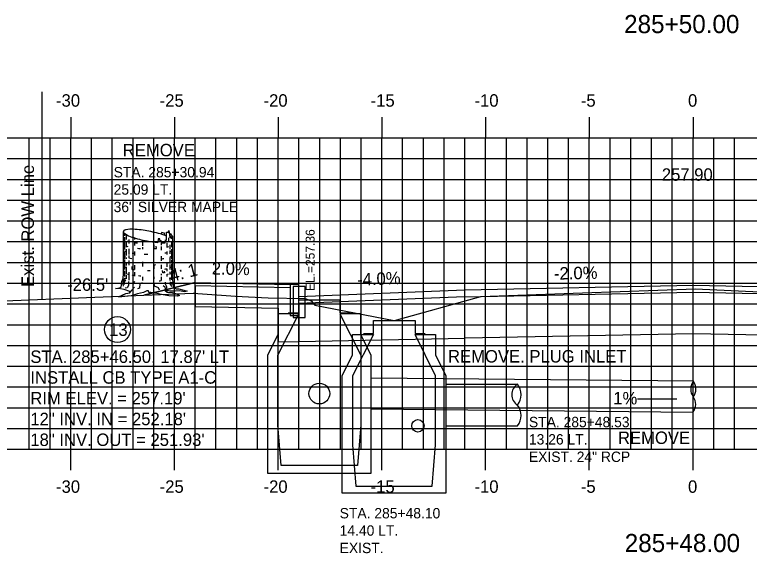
# Model space of a CAD drawing. Extents: x 856680 to 856850, y 366268 to 366378.
# Drawn here: x 856730.41 to 856765.83, y 366297.22 to 366323.17 of the extents above; entities that cross this region are included whole.
import ezdxf

# ---------------------------------------------------------------- set-up
doc = ezdxf.new("R2010")
doc.units = 0
for name, color, linetype in [('ANNOTATION', 7, 'Continuous'), ('D_Curb_Type_1_Lt', 7, 'Continuous'), ('D_Drainage_CB_TypeA1-B1', 7, 'Continuous'), ('D_Drainage_Culvert', 7, 'Continuous'), ('D_Drainage_Text', 7, 'Continuous'), ('D_Roadway_Centerline_Text', 7, 'Continuous'), ('D_Roadway_Edge_Shoulder', 7, 'Continuous'), ('D_Roadway_FinishedGrade', 7, 'Continuous'), ('D_Roadway_Sidewalks_Paved', 7, 'Continuous'), ('D_Roadway_SubGrade', 7, 'Continuous'), ('D_Text_Monospaced', 7, 'Continuous'), ('D_Text_Standard', 7, 'Continuous'), ('E_ROW_Line', 7, 'Continuous'), ('H_V ANNOTATION', 7, 'Continuous'), ('JUNK FILL', 7, 'Continuous'), ('MAJOR', 7, 'Continuous'), ('MINOR', 7, 'Continuous'), ('PDRAIN', 7, 'Continuous'), ('S_Curb_Type_2', 7, 'Continuous'), ('S_Drainage_CB', 7, 'Continuous'), ('S_Drainage_Culvert_Top', 7, 'Continuous'), ('S_Drainage_Invert', 7, 'Continuous'), ('S_Roadway_Centerline', 7, 'Continuous'), ('S_Trees_Decid_Pay', 7, 'Continuous')]:
    doc.layers.add(name, color=color, linetype=linetype)

msp = doc.modelspace()

# ---------------------------------------------------------------- linework, layer by layer
at = {"layer": 'ANNOTATION'}
msp.add_line((856760.442, 366304.662), (856762.341, 366304.662), dxfattribs=at)
at = {"layer": 'D_Curb_Type_1_Lt'}
msp.add_lwpolyline([(856743.7, 366310.179), (856743.7, 366308.679), (856744.116, 366308.679), (856744.116, 366310.179)], close=True, dxfattribs=at)
at = {"layer": 'D_Drainage_CB_TypeA1-B1'}
for p, q in [((856743.099, 366308.761), (856743.099, 366307.744)), ((856743.099, 366306.76), (856744.116, 366308.761)), ((856744.116, 366308.761), (856743.099, 366308.761)), ((856747.102, 366308.761), (856746.085, 366308.761)), ((856746.085, 366308.761), (856747.102, 366306.76)), ((856747.102, 366307.744), (856747.102, 366308.761)), ((856743.099, 366307.744), (856742.607, 366306.76)), ((856747.594, 366306.76), (856747.102, 366307.744)), ((856742.607, 366306.76), (856742.607, 366301.084)), ((856743.099, 366303.414), (856743.099, 366306.76)), ((856747.102, 366306.76), (856747.102, 366303.414)), ((856747.594, 366301.084), (856747.594, 366306.76)), ((856743.263, 366301.445), (856743.099, 366303.414)), ((856747.102, 366303.414), (856746.938, 366301.445)), ((856746.938, 366301.445), (856743.263, 366301.445)), ((856742.607, 366301.084), (856747.594, 366301.084))]:
    msp.add_line(p, q, dxfattribs=at)
msp.add_lwpolyline([(856743.591, 366308.803), (856744.116, 366308.803), (856744.116, 366309.426), (856746.085, 366309.426), (856746.085, 366308.803), (856746.61, 366308.803)], dxfattribs=at)
at = {"layer": 'D_Drainage_Culvert'}
for p, q in [((856763.132, 366305.511), (856747.609, 366305.666)), ((856763.117, 366304.011), (856747.594, 366304.166))]:
    msp.add_line(p, q, dxfattribs=at)
for centre, radius, start, end in [((856763.628, 366305.131), 0.625, 142.5572, 216.297), ((856762.615, 366305.137), 0.638, 323.5548, 35.9163), ((856762.629, 366304.394), 0.617, 321.892, 36.5542)]:
    msp.add_arc(centre, radius, start, end, dxfattribs=at)
at = {"layer": 'D_Drainage_Text'}
msp.add_circle((856735.365, 366307.999), 0.625, dxfattribs=at)
at = {"layer": 'D_Roadway_Edge_Shoulder'}
msp.add_lwpolyline([(856744.116, 366309.596), (856752.116, 366309.916), (856763.116, 366310.136), (856774.116, 366309.916), (856782.117, 366309.596)], dxfattribs=at)
at = {"layer": 'D_Roadway_FinishedGrade'}
msp.add_line((856736.635, 366309.652), (856739.111, 366310.271), dxfattribs=at)
at = {"layer": 'D_Roadway_Sidewalks_Paved'}
msp.add_lwpolyline([(856739.111, 366310.271), (856743.7, 366310.179), (856743.7, 366310.012), (856739.111, 366310.104)], close=True, dxfattribs=at)
at = {"layer": 'D_Roadway_SubGrade'}
msp.add_lwpolyline([(856739.111, 366310.104), (856739.111, 366309.104), (856743.116, 366309.024), (856743.116, 366307.402), (856744.116, 366307.422)], dxfattribs=at)
for points in [[(856752.116, 366307.582), (856752.116, 366309.582), (856763.116, 366309.802), (856774.116, 366309.582), (856774.116, 366307.582), (856763.116, 366307.802)], [(856752.116, 366309.582), (856744.116, 366309.262), (856744.116, 366307.422), (856752.116, 366307.582)]]:
    msp.add_lwpolyline(points, close=True, dxfattribs=at)
at = {"layer": 'E_ROW_Line'}
msp.add_line((856731.739, 366309.453), (856731.739, 366319.453), dxfattribs=at)
at = {"layer": 'JUNK FILL'}
msp.add_lwpolyline([(856739.116, 366309.749), (856739.116, 366310.271), (856739.111, 366310.271), (856736.635, 366309.652), (856739.021, 366309.749)], close=True, dxfattribs=at)
at = {"layer": 'MAJOR'}
for p, q in [((856733.116, 366318.238), (856733.116, 366317.236)), ((856738.116, 366318.238), (856738.116, 366317.236)), ((856743.116, 366318.238), (856743.116, 366317.236)), ((856748.116, 366318.238), (856748.116, 366317.236)), ((856753.116, 366318.238), (856753.116, 366317.236)), ((856758.116, 366318.238), (856758.116, 366317.236)), ((856763.116, 366318.238), (856763.116, 366317.236)), ((856693.116, 366317.236), (856833.116, 366317.236)), ((856693.116, 366317.236), (856833.116, 366317.236)), ((856733.116, 366302.236), (856733.116, 366317.236)), ((856738.116, 366302.236), (856738.116, 366317.236)), ((856743.116, 366302.236), (856743.116, 366317.236)), ((856748.116, 366302.236), (856748.116, 366317.236)), ((856753.116, 366302.236), (856753.116, 366317.236)), ((856758.116, 366302.236), (856758.116, 366317.236)), ((856763.116, 366302.236), (856763.116, 366317.236)), ((856693.116, 366312.236), (856833.116, 366312.236)), ((856693.116, 366307.236), (856833.116, 366307.236)), ((856693.116, 366302.236), (856833.116, 366302.236)), ((856693.116, 366302.236), (856833.116, 366302.236)), ((856733.116, 366301.234), (856733.116, 366302.236)), ((856738.116, 366301.234), (856738.116, 366302.236)), ((856743.116, 366301.234), (856743.116, 366302.236)), ((856748.116, 366301.234), (856748.116, 366302.236)), ((856753.116, 366301.234), (856753.116, 366302.236)), ((856758.116, 366301.234), (856758.116, 366302.236)), ((856763.116, 366301.234), (856763.116, 366302.236))]:
    msp.add_line(p, q, dxfattribs=at)
at = {"layer": 'MINOR'}
for p, q in [((856731.116, 366302.236), (856731.116, 366317.236)), ((856732.116, 366302.236), (856732.116, 366317.236)), ((856734.116, 366302.236), (856734.116, 366317.236)), ((856735.116, 366302.236), (856735.116, 366317.236)), ((856736.116, 366302.236), (856736.116, 366317.236)), ((856737.116, 366302.236), (856737.116, 366317.236)), ((856739.116, 366302.236), (856739.116, 366317.236)), ((856740.116, 366302.236), (856740.116, 366317.236)), ((856741.116, 366302.236), (856741.116, 366317.236)), ((856742.116, 366302.236), (856742.116, 366317.236)), ((856744.116, 366302.236), (856744.116, 366317.236)), ((856745.116, 366302.236), (856745.116, 366317.236)), ((856746.116, 366302.236), (856746.116, 366317.236)), ((856747.116, 366302.236), (856747.116, 366317.236)), ((856749.116, 366302.236), (856749.116, 366317.236)), ((856750.116, 366302.236), (856750.116, 366317.236)), ((856751.116, 366302.236), (856751.116, 366317.236)), ((856752.116, 366302.236), (856752.116, 366317.236)), ((856754.116, 366302.236), (856754.116, 366317.236)), ((856755.116, 366302.236), (856755.116, 366317.236)), ((856756.116, 366302.236), (856756.116, 366317.236)), ((856757.116, 366302.236), (856757.116, 366317.236)), ((856759.116, 366302.236), (856759.116, 366317.236)), ((856760.116, 366302.236), (856760.116, 366317.236)), ((856761.116, 366302.236), (856761.116, 366317.236)), ((856762.116, 366302.236), (856762.116, 366317.236)), ((856764.116, 366302.236), (856764.116, 366317.236)), ((856765.116, 366302.236), (856765.116, 366317.236)), ((856693.116, 366316.236), (856833.116, 366316.236)), ((856693.116, 366315.236), (856833.116, 366315.236)), ((856693.116, 366314.236), (856833.116, 366314.236)), ((856693.116, 366313.236), (856833.116, 366313.236)), ((856693.116, 366311.236), (856833.116, 366311.236)), ((856693.116, 366310.236), (856833.116, 366310.236)), ((856693.116, 366309.236), (856833.116, 366309.236)), ((856693.116, 366308.236), (856833.116, 366308.236)), ((856693.116, 366306.236), (856833.116, 366306.236)), ((856693.116, 366305.236), (856833.116, 366305.236)), ((856693.116, 366304.236), (856833.116, 366304.236)), ((856693.116, 366303.236), (856833.116, 366303.236))]:
    msp.add_line(p, q, dxfattribs=at)
at = {"layer": 'PDRAIN'}
msp.add_circle((856745.1, 366304.916), 0.5, dxfattribs=at)
at = {"layer": 'S_Curb_Type_2'}
msp.add_lwpolyline([(856744.423, 366310.081), (856743.839, 366310.081), (856743.839, 366308.581), (856744.423, 366308.581)], close=True, dxfattribs=at)
at = {"layer": 'S_Drainage_CB'}
for p, q in [((856746.697, 366306.782), (856746.697, 366307.766)), ((856746.697, 366307.766), (856747.714, 366307.766)), ((856747.714, 366307.766), (856746.697, 366305.765)), ((856749.716, 366307.766), (856750.7, 366307.766)), ((856750.7, 366305.765), (856749.716, 366307.766)), ((856750.7, 366307.766), (856750.7, 366306.782)), ((856746.205, 366305.765), (856746.697, 366306.782)), ((856750.7, 366306.782), (856751.192, 366305.765)), ((856746.205, 366300.122), (856746.205, 366305.765)), ((856746.697, 366305.765), (856746.697, 366302.451)), ((856750.7, 366302.451), (856750.7, 366305.765)), ((856751.192, 366305.765), (856751.192, 366300.122)), ((856746.697, 366302.451), (856746.861, 366300.45)), ((856750.536, 366300.45), (856750.7, 366302.451)), ((856746.861, 366300.45), (856750.536, 366300.45)), ((856751.192, 366300.122), (856746.205, 366300.122))]:
    msp.add_line(p, q, dxfattribs=at)
msp.add_lwpolyline([(856747.222, 366307.808), (856747.714, 366307.808), (856747.714, 366308.431), (856749.716, 366308.431), (856749.716, 366307.808), (856750.208, 366307.808)], dxfattribs=at)
at = {"layer": 'S_Drainage_Culvert_Top'}
for p, q in [((856751.192, 366305.363), (856754.658, 366305.363)), ((856751.192, 366303.363), (856754.658, 366303.363))]:
    msp.add_line(p, q, dxfattribs=at)
for centre, radius, start, end in [((856754.955, 366304.863), 0.582, 120.7154, 239.2846), ((856753.991, 366304.863), 0.833, 323.1301, 36.8699), ((856753.991, 366303.863), 0.833, 323.1301, 36.8699)]:
    msp.add_arc(centre, radius, start, end, dxfattribs=at)
at = {"layer": 'S_Drainage_Invert'}
msp.add_circle((856749.853, 366303.363), 0.3, dxfattribs=at)
at = {"layer": 'S_Roadway_Centerline'}
msp.add_lwpolyline([(856729.519, 366309.362), (856739.021, 366309.749), (856741.05, 366309.607), (856742.639, 366309.528), (856744.423, 366309.498), (856744.707, 366309.391), (856744.882, 366309.174), (856748.7, 366308.435), (856748.73, 366308.436), (856752.889, 366309.59), (856757.791, 366309.768), (856763.242, 366309.958), (856768.411, 366309.721)], dxfattribs=at)
at = {"layer": 'S_Trees_Decid_Pay'}
for p, q in [((856735.702, 366312.63), (856735.702, 366312.51)), ((856735.702, 366312.458), (856735.702, 366312.244)), ((856735.782, 366312.586), (856735.782, 366312.333)), ((856735.702, 366312.199), (856735.702, 366311.861)), ((856735.782, 366312.236), (856735.782, 366311.972)), ((856735.915, 366312.333), (856735.915, 366312.141)), ((856736.187, 366312.419), (856736.187, 366312.333)), ((856736.187, 366312.191), (856736.187, 366312.052)), ((856736.57, 366312.318), (856736.57, 366312.038)), ((856737.481, 366312.18), (856737.481, 366312.061)), ((856737.742, 366312.178), (856737.742, 366311.974)), ((856737.827, 366312.427), (856737.827, 366312.252)), ((856737.976, 366312.227), (856737.976, 366311.972)), ((856735.702, 366311.744), (856735.702, 366311.383)), ((856735.782, 366311.875), (856735.782, 366311.567)), ((856735.915, 366311.89), (856735.915, 366311.612)), ((856736.187, 366311.766), (856736.187, 366311.575)), ((856736.57, 366311.972), (856736.57, 366311.869)), ((856737.116, 366312.081), (856737.116, 366311.901)), ((856737.243, 366311.909), (856737.238, 366312.016)), ((856737.481, 366312.009), (856737.481, 366311.824)), ((856737.742, 366311.766), (856737.742, 366311.612)), ((856737.89, 366312.081), (856737.89, 366311.869)), ((856737.89, 366311.804), (856737.89, 366311.655)), ((856737.976, 366311.875), (856737.976, 366311.406)), ((856735.782, 366311.478), (856735.782, 366311.412)), ((856735.915, 366311.567), (856735.915, 366311.458)), ((856737.481, 366311.538), (856737.481, 366311.31)), ((856737.89, 366311.478), (856737.89, 366311.178)), ((856735.702, 366311.346), (856735.702, 366310.897)), ((856735.782, 366311.178), (856735.782, 366311.081)), ((856735.782, 366311.029), (856735.782, 366310.669)), ((856735.915, 366311.323), (856735.915, 366311.095)), ((856736.187, 366311.095), (856736.187, 366310.887)), ((856736.57, 366311.258), (856736.57, 366311.037)), ((856737.116, 366311.123), (856737.116, 366310.926)), ((856737.481, 366311.111), (856737.481, 366310.926)), ((856737.742, 366311.249), (856737.742, 366311.029)), ((856737.89, 366311.14), (856737.89, 366310.897)), ((856737.976, 366311.355), (856737.976, 366311.221)), ((856737.976, 366311.163), (856737.976, 366310.838)), ((856735.702, 366310.832), (856735.702, 366310.55)), ((856735.915, 366310.766), (856735.915, 366310.382)), ((856736.187, 366310.766), (856736.187, 366310.566)), ((856737.481, 366310.691), (856737.481, 366310.615)), ((856737.742, 366310.93), (856737.742, 366310.809)), ((856737.89, 366310.787), (856737.89, 366310.646)), ((856737.976, 366310.809), (856737.976, 366310.389)), ((856735.782, 366310.617), (856735.782, 366310.451)), ((856736.57, 366310.537), (856736.57, 366310.364)), ((856737.116, 366310.543), (856737.116, 366310.44)), ((856737.481, 366310.537), (856737.481, 366310.364)), ((856737.742, 366310.658), (856737.742, 366310.56)), ((856737.89, 366310.514), (856737.89, 366310.358)), ((856736.192, 366310.309), (856736.112, 366310.177)), ((856737.973, 366310.286), (856737.987, 366310.168))]:
    msp.add_line(p, q, dxfattribs=at)
for points in [[(856738.027, 366312.501), (856738.027, 366310.364), (856738.047, 366310.222), (856738.053, 366310.096), (856738.096, 366310.01), (856738.189, 366309.96), (856738.325, 366309.96), (856738.568, 366309.905), (856738.735, 366309.856), (856738.592, 366309.825), (856738.356, 366309.862), (856738.146, 366309.85), (856737.884, 366309.856), (856737.76, 366309.874), (856737.73, 366309.831), (856737.668, 366309.874), (856737.767, 366309.806), (856738.002, 366309.781), (856738.232, 366309.72), (856738.362, 366309.649), (856738.263, 366309.606), (856737.841, 366309.625), (856737.563, 366309.668), (856737.264, 366309.745), (856736.978, 366309.781), (856736.873, 366309.781), (856736.855, 366309.862), (856736.787, 366309.868), (856736.62, 366309.781), (856736.334, 366309.726), (856736.035, 366309.619), (856735.576, 366309.569), (856735.422, 366309.582), (856735.764, 366309.732), (856735.967, 366309.763), (856735.955, 366309.837), (856735.696, 366309.936), (856735.52, 366309.967), (856735.279, 366309.979), (856735.478, 366310.016), (856735.539, 366310.053), (856735.564, 366310.14), (856735.576, 366310.309), (856735.621, 366310.395), (856735.65, 366310.636), (856735.65, 366312.722)], [(856737.648, 366312.54), (856737.627, 366312.647), (856737.495, 366312.678), (856737.488, 366312.59)], [(856737.671, 366312.174), (856737.678, 366312.318), (856737.724, 366312.31), (856737.738, 366312.685), (856737.833, 366312.693), (856737.847, 366312.773), (856737.884, 366312.436), (856737.93, 366312.53), (856737.95, 366312.376), (856738.027, 366312.501), (856738.021, 366312.312)], [(856738.027, 366312.501), (856737.981, 366312.524), (856737.959, 366312.59), (856737.907, 366312.613), (856737.873, 366312.538)], [(856737.509, 366312.178), (856737.472, 366312.281), (856737.407, 366312.287), (856737.407, 366312.369), (856737.333, 366312.376), (856737.308, 366312.195)], [(856736.073, 366310.901), (856736.075, 366310.978), (856736.083, 366311.044)], [(856737.619, 366310.809), (856737.627, 366310.735), (856737.553, 366310.729), (856737.539, 366310.846)], [(856735.7, 366310.478), (856735.64, 366310.317), (856735.626, 366310.191), (856735.634, 366310.094)], [(856735.757, 366310.397), (856735.686, 366310.294), (856735.686, 366310.168)], [(856735.898, 366310.323), (856735.898, 366310.117), (856735.84, 366310.008), (856735.743, 366309.991)], [(856735.967, 366309.763), (856736.054, 366309.905), (856736.186, 366310.047)], [(856736.552, 366310.249), (856736.449, 366310.197), (856736.435, 366309.991), (856736.332, 366309.962)], [(856737.118, 366310.257), (856737.135, 366310.103), (856737.333, 366310.022), (856737.378, 366309.919)], [(856737.57, 366310.121), (856737.644, 366310.053), (856737.662, 366309.955), (856737.668, 366309.874)], [(856737.76, 366309.874), (856737.742, 366310.053), (856737.68, 366310.189), (856737.687, 366310.29)], [(856737.907, 366310.294), (856737.913, 366310.168), (856737.995, 366310.074)]]:
    msp.add_lwpolyline(points, dxfattribs=at)
for centre, radius, start, end in [((856735.881, 366312.339), 0.48, 101.7221, 110.0157), ((856736.048, 366311.536), 1.299, 86.3056, 101.7221), ((856735.737, 366306.72), 6.126, 79.2221, 86.3056), ((856735.696, 366312.722), 0.0467, 169.2221, 180.9043), ((856735.704, 366312.722), 0.0544, 180.9043, 191.7221), ((856735.696, 366312.722), 0.0467, 157.54, 169.2221), ((856735.714, 366312.724), 0.0645, 191.7221, 204.3989), ((856735.703, 366312.719), 0.0544, 146.7221, 157.54), ((856735.753, 366312.742), 0.107, 204.3989, 214.2221), ((856735.712, 366312.713), 0.0645, 134.0453, 146.7221), ((856735.8, 366312.774), 0.164, 214.2221, 228.4286), ((856735.741, 366312.683), 0.107, 124.2221, 134.0453), ((856735.773, 366312.636), 0.164, 110.0157, 124.2221), ((856736.009, 366313.01), 0.48, 228.4286, 236.7221), ((856736.459, 366313.695), 1.299, 236.7221, 252.1387), ((856737.939, 366318.289), 6.126, 252.1387, 259.2221), ((856735.737, 366306.72), 6.126, 72.1387, 79.2221), ((856737.217, 366311.314), 1.299, 66.6931, 72.1387), ((856735.704, 366312.395), 0.0554, 191.6815, 202.5), ((856735.705, 366312.134), 0.0554, 191.6815, 202.5), ((856735.713, 366312.399), 0.0657, 202.5, 215.1737), ((856735.714, 366312.138), 0.0657, 202.5, 215.1737), ((856735.749, 366312.424), 0.109, 215.1737, 225), ((856735.75, 366312.163), 0.109, 215.1737, 225), ((856735.789, 366312.465), 0.166, 225, 238.33), ((856735.79, 366312.204), 0.166, 225, 239.1924), ((856736.261, 366313.484), 1.292, 250.9084, 254.4349), ((856736.837, 366318.072), 5.916, 263.6913, 265.0485), ((856737.939, 366318.289), 6.126, 259.2221, 264.0853), ((856737.939, 366318.289), 6.126, 265.9754, 266.3056), ((856737.628, 366313.472), 1.299, 266.3056, 271.8711), ((856737.886, 366312.204), 0.166, 300.8076, 315), ((856737.926, 366312.163), 0.109, 315, 324.8263), ((856737.962, 366312.138), 0.0657, 324.8263, 337.5), ((856737.971, 366312.134), 0.0554, 337.5, 348.3185), ((856737.979, 366312.133), 0.0476, 348.3185, 0), ((856735.79, 366311.94), 0.166, 238.3999, 239.1924), ((856735.953, 366312.477), 0.484, 239.1924, 242.5838), ((856735.953, 366312.213), 0.484, 239.1924, 247.5), ((856736.262, 366313.223), 1.292, 247.5, 251.9171), ((856736.262, 366312.96), 1.292, 247.5, 248.1929), ((856736.838, 366317.811), 5.916, 265.1076, 266.4618), ((856736.838, 366317.811), 5.916, 272.6957, 273.9224), ((856737.414, 366313.223), 1.292, 284.7144, 289.3881), ((856737.414, 366312.96), 1.292, 291.6463, 292.5), ((856737.723, 366312.213), 0.484, 292.5, 300.8076), ((856737.886, 366311.94), 0.166, 300.8076, 302.9622), ((856735.705, 366311.613), 0.0554, 191.6815, 202.5), ((856735.714, 366311.617), 0.0657, 202.5, 215.1737), ((856735.75, 366311.642), 0.109, 215.1737, 225), ((856735.79, 366311.683), 0.166, 225, 239.1924), ((856735.953, 366311.956), 0.484, 239.1924, 245.3628), ((856736.262, 366312.702), 1.292, 254.3895, 260.7435), ((856736.262, 366312.96), 1.292, 261.6338, 262.8454), ((856736.838, 366317.548), 5.916, 262.8454, 263.6816), ((856736.838, 366317.548), 5.916, 268.2292, 269.8838), ((856736.838, 366317.29), 5.916, 276.2405, 277.1546), ((856737.414, 366312.702), 1.292, 277.1546, 278.1274), ((856737.414, 366312.96), 1.292, 280.7368, 284.7144), ((856737.414, 366312.702), 1.292, 291.5158, 292.5), ((856737.723, 366311.956), 0.484, 294.2275, 300.8076), ((856737.886, 366311.683), 0.166, 300.8076, 315), ((856737.926, 366311.642), 0.109, 315, 324.8263), ((856737.962, 366311.617), 0.0657, 324.8263, 337.5), ((856737.971, 366311.613), 0.0554, 337.5, 348.3185), ((856737.979, 366311.612), 0.0476, 348.3185, 0), ((856735.705, 366311.356), 0.0554, 191.6815, 202.5), ((856735.705, 366311.091), 0.0554, 191.6815, 202.5), ((856735.714, 366311.36), 0.0657, 202.5, 215.1737), ((856735.75, 366311.385), 0.109, 215.1737, 225), ((856735.79, 366311.426), 0.166, 225, 237.9306), ((856736.262, 366312.445), 1.292, 249.8999, 254.3895), ((856736.838, 366317.033), 5.916, 272.6957, 273.7279), ((856737.414, 366312.445), 1.292, 288.201, 292.5), ((856737.886, 366311.426), 0.166, 300.8076, 315), ((856737.886, 366311.16), 0.166, 300.8076, 315), ((856737.926, 366311.385), 0.109, 315, 324.8263), ((856737.926, 366311.119), 0.109, 315, 324.8263), ((856737.962, 366311.36), 0.0657, 324.8263, 337.5), ((856737.962, 366311.094), 0.0657, 324.8263, 337.5), ((856737.971, 366311.356), 0.0554, 337.5, 348.3185), ((856737.971, 366311.091), 0.0554, 337.5, 348.3185), ((856737.979, 366311.355), 0.0476, 348.3185, 0), ((856737.979, 366311.089), 0.0476, 348.3185, 0), ((856735.705, 366310.819), 0.0554, 191.6815, 202.5), ((856735.714, 366310.823), 0.0657, 202.5, 215.1737), ((856735.75, 366310.848), 0.109, 215.1737, 225), ((856735.79, 366310.888), 0.166, 225, 237.9306), ((856735.79, 366311.16), 0.166, 237.9306, 239.1924), ((856735.953, 366311.433), 0.484, 239.1924, 247.5), ((856736.262, 366311.907), 1.292, 250.8466, 254.3895), ((856736.262, 366312.179), 1.292, 261.6205, 262.8454), ((856736.838, 366316.767), 5.916, 262.8454, 263.6816), ((856736.838, 366316.767), 5.916, 269.7243, 270), ((856736.838, 366316.767), 5.916, 270, 271.0793), ((856737.414, 366312.179), 1.292, 280.7537, 284.7144), ((856737.414, 366311.907), 1.292, 284.7144, 288.6336), ((856737.414, 366312.179), 1.292, 291.6463, 292.5), ((856737.723, 366311.433), 0.484, 292.5, 300.8076), ((856737.723, 366311.161), 0.484, 292.5, 297.266), ((856735.953, 366310.904), 0.484, 243.4501, 247.5), ((856736.253, 366311.654), 1.292, 247.9396, 248.6304), ((856736.262, 366311.907), 1.292, 261.6338, 262.8454), ((856736.838, 366316.495), 5.916, 262.8454, 263.6816), ((856736.838, 366316.495), 5.916, 265.539, 266.7363), ((856736.838, 366316.238), 5.916, 275.2344, 276.2169), ((856737.414, 366311.65), 1.292, 291.6463, 292.5), ((856737.723, 366310.904), 0.484, 292.5, 300.8076), ((856737.886, 366310.631), 0.166, 300.8076, 315), ((856737.926, 366310.59), 0.109, 315, 324.8263), ((856737.962, 366310.565), 0.0657, 324.8263, 337.5), ((856737.971, 366310.561), 0.0554, 337.5, 348.3185), ((856737.979, 366310.56), 0.0476, 348.3185, 0)]:
    msp.add_arc(centre, radius, start, end, dxfattribs=at)

# ---------------------------------------------------------------- texts
at = {"layer": 'ANNOTATION'}
for s, p in [('REMOVE', (856735.623, 366316.346)), ('REMOVE. PLUG INLET', (856751.304, 366306.413)), ('REMOVE', (856759.498, 366302.489))]:
    msp.add_text(s, height=0.6, dxfattribs=at).set_placement(p)
for s, rotation, p in [('4: 1', 14.0362, (856737.975, 366310.296)), ('2.0%', 358.8542, (856739.909, 366310.655)), ('-2.0%', 1.1458, (856756.419, 366310.402)), ('-4.0%', 2.2906, (856746.932, 366310.109)), ('1%', 359.4271, (856759.268, 366304.401))]:
    msp.add_text(s, height=0.6, rotation=rotation, dxfattribs=at).set_placement(p)
at = {"layer": 'D_Drainage_Text'}
for s, p in [("STA. 285+46.50, 17.87' LT", (856731.166, 366306.393)), ('INSTALL CB TYPE A1-C', (856731.166, 366305.393)), ("RIM ELEV. = 257.19'", (856731.166, 366304.393)), ('12" INV. IN = 252.18\'', (856731.166, 366303.393)), ('18" INV. OUT = 251.93\'', (856731.166, 366302.393))]:
    msp.add_text(s, height=0.6, dxfattribs=at).set_placement(p)
at = {"layer": 'D_Roadway_Centerline_Text'}
msp.add_text('257.90', height=0.6, dxfattribs=at).set_placement((856761.612, 366315.168))
at = {"layer": 'D_Text_Monospaced'}
for s, height, p in [('STA. 285+30.94', 0.49998, (856735.183, 366315.331)), ('25.09 LT.', 0.5, (856735.183, 366314.497)), ('36" SILVER MAPLE', 0.49998, (856735.183, 366313.657)), ('STA. 285+48.53', 0.49998, (856755.205, 366303.296)), ('13.26 LT.', 0.5, (856755.205, 366302.462)), ('EXIST. 24" RCP', 0.49998, (856755.205, 366301.622)), ('STA. 285+48.10', 0.49998, (856746.08, 366298.904)), ('14.40 LT.', 0.5, (856746.08, 366298.07)), ('EXIST. ', 0.5, (856746.08, 366297.23))]:
    msp.add_text(s, height=height, dxfattribs=at).set_placement(p)
at = {"layer": 'D_Text_Standard'}
msp.add_text(' EL.=257.36', height=0.4335, rotation=90, dxfattribs=at).set_placement((856744.873, 366309.69))
msp.add_text("-26.5'", height=0.6, dxfattribs=at).set_placement((856732.942, 366309.864))
at = {"layer": 'E_ROW_Line'}
msp.add_text('Exist. ROW Line', height=0.6, rotation=90, dxfattribs=at).set_placement((856731.339, 366310.053))
at = {"layer": 'H_V ANNOTATION'}
for s, height, p in [('285+50.00', 0.875, (856759.792, 366322.28)), ('-30', 0.6, (856732.404, 366318.736)), ('-25', 0.6, (856737.402, 366318.736)), ('-20', 0.6, (856742.41, 366318.736)), ('-15', 0.6, (856747.573, 366318.736)), ('-10', 0.6, (856752.581, 366318.736)), ('-5', 0.6, (856757.707, 366318.736)), ('0', 0.6, (856762.875, 366318.736)), ('13', 0.6, (856734.966, 366307.695)), ('-30', 0.6, (856732.404, 366300.136)), ('-25', 0.6, (856737.402, 366300.136)), ('-20', 0.6, (856742.41, 366300.136)), ('-15', 0.6, (856747.573, 366300.136)), ('-10', 0.6, (856752.581, 366300.136)), ('-5', 0.6, (856757.707, 366300.136)), ('0', 0.6, (856762.875, 366300.136)), ('285+48.00', 0.875, (856759.823, 366297.28))]:
    msp.add_text(s, height=height, dxfattribs=at).set_placement(p)
at = {"layer": 'S_Roadway_Centerline'}
for s, p in [('C', (856763.237, 366309.958)), ('L', (856763.242, 366309.951))]:
    msp.add_text(s, height=0.0146, dxfattribs=at).set_placement(p)

doc.saveas('drawing.dxf')
